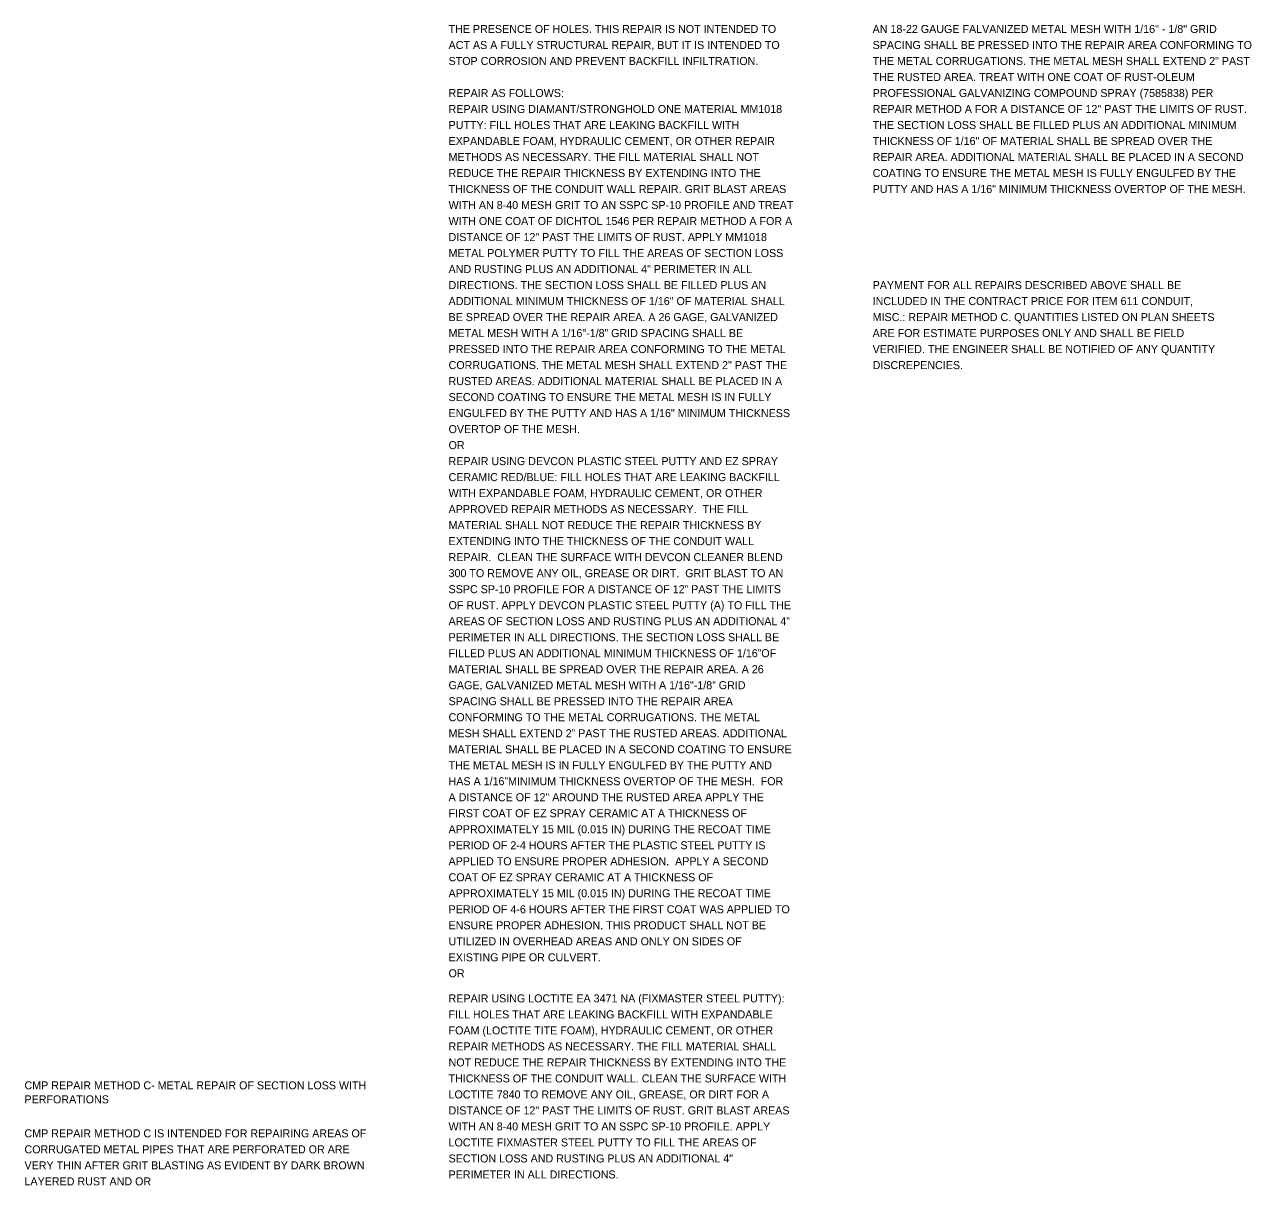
# Model space of a CAD drawing. Extents: x 0 to 34, y -22.7 to 22.
# Drawn here: x 9.82 to 31.29, y -22.66 to -2.35 of the extents above; entities that cross this region are included whole.
import ezdxf

# ---------------------------------------------------------------- set-up
doc = ezdxf.new("R2010")
doc.units = 0
doc.layers.add('SH_Text', color=7, linetype='Continuous')

msp = doc.modelspace()

# ---------------------------------------------------------------- texts
at = {"layer": 'SH_Text'}
for s, p in [('THE PRESENCE OF HOLES. THIS REPAIR IS NOT INTENDED TO ', (17.24, -2.502)), ('AN 18-22 GAUGE FALVANIZED METAL MESH WITH 1/16" - 1/8" GRID ', (24.66, -2.502)), ('ACT AS A FULLY STRUCTURAL REPAIR, BUT IT IS INTENDED TO ', (17.24, -2.782)), ('SPACING SHALL BE PRESSED INTO THE REPAIR AREA CONFORMING TO ', (24.66, -2.782)), ('STOP CORROSION AND PREVENT BACKFILL INFILTRATION.', (17.24, -3.062)), ('THE METAL CORRUGATIONS. THE METAL MESH SHALL EXTEND 2" PAST ', (24.66, -3.062)), ('THE RUSTED AREA. TREAT WITH ONE COAT OF RUST-OLEUM ', (24.66, -3.342)), ('REPAIR AS FOLLOWS:', (17.24, -3.622)), ('PROFESSIONAL GALVANIZING COMPOUND SPRAY (7585838) PER ', (24.66, -3.622)), ('REPAIR USING DIAMANT/STRONGHOLD ONE MATERIAL MM1018 ', (17.24, -3.902)), ('REPAIR METHOD A FOR A DISTANCE OF 12" PAST THE LIMITS OF RUST. ', (24.66, -3.902)), ('PUTTY: FILL HOLES THAT ARE LEAKING BACKFILL WITH ', (17.24, -4.182)), ('THE SECTION LOSS SHALL BE FILLED PLUS AN ADDITIONAL MINIMUM ', (24.66, -4.182)), ('EXPANDABLE FOAM, HYDRAULIC CEMENT, OR OTHER REPAIR ', (17.24, -4.462)), ('THICKNESS OF 1/16" OF MATERIAL SHALL BE SPREAD OVER THE ', (24.66, -4.462)), ('METHODS AS NECESSARY. THE FILL MATERIAL SHALL NOT ', (17.24, -4.742)), ('REPAIR AREA. ADDITIONAL MATERIAL SHALL BE PLACED IN A SECOND ', (24.66, -4.742)), ('REDUCE THE REPAIR THICKNESS BY EXTENDING INTO THE ', (17.24, -5.022)), ('COATING TO ENSURE THE METAL MESH IS FULLY ENGULFED BY THE ', (24.66, -5.022)), ('THICKNESS OF THE CONDUIT WALL REPAIR. GRIT BLAST AREAS ', (17.24, -5.302)), ('PUTTY AND HAS A 1/16" MINIMUM THICKNESS OVERTOP OF THE MESH.', (24.66, -5.302)), ('WITH AN 8-40 MESH GRIT TO AN SSPC SP-10 PROFILE AND TREAT ', (17.24, -5.582)), ('WITH ONE COAT OF DICHTOL 1546 PER REPAIR METHOD A FOR A ', (17.24, -5.862)), ('DISTANCE OF 12" PAST THE LIMITS OF RUST. APPLY MM1018 ', (17.24, -6.142)), ('METAL POLYMER PUTTY TO FILL THE AREAS OF SECTION LOSS ', (17.24, -6.422)), ('AND RUSTING PLUS AN ADDITIONAL 4" PERIMETER IN ALL ', (17.24, -6.702)), ('DIRECTIONS. THE SECTION LOSS SHALL BE FILLED PLUS AN ', (17.24, -6.982)), ('PAYMENT FOR ALL REPAIRS DESCRIBED ABOVE SHALL BE ', (24.66, -6.982)), ('ADDITIONAL MINIMUM THICKNESS OF 1/16" OF MATERIAL SHALL ', (17.24, -7.262)), ('INCLUDED IN THE CONTRACT PRICE FOR ITEM 611 CONDUIT, ', (24.66, -7.262)), ('BE SPREAD OVER THE REPAIR AREA. A 26 GAGE, GALVANIZED ', (17.24, -7.542)), ('MISC.: REPAIR METHOD C. QUANTITIES LISTED ON PLAN SHEETS ', (24.66, -7.542)), ('METAL MESH WITH A 1/16"-1/8” GRID SPACING SHALL BE ', (17.24, -7.822)), ('ARE FOR ESTIMATE PURPOSES ONLY AND SHALL BE FIELD ', (24.66, -7.822)), ('PRESSED INTO THE REPAIR AREA CONFORMING TO THE METAL ', (17.24, -8.102)), ('VERIFIED. THE ENGINEER SHALL BE NOTIFIED OF ANY QUANTITY ', (24.66, -8.102)), ('CORRUGATIONS. THE METAL MESH SHALL EXTEND 2" PAST THE ', (17.24, -8.382)), ('DISCREPENCIES.', (24.66, -8.382)), ('RUSTED AREAS. ADDITIONAL MATERIAL SHALL BE PLACED IN A ', (17.24, -8.662)), ('SECOND COATING TO ENSURE THE METAL MESH IS IN FULLY ', (17.24, -8.942)), ('ENGULFED BY THE PUTTY AND HAS A 1/16" MINIMUM THICKNESS ', (17.24, -9.222)), ('OVERTOP OF THE MESH. ', (17.24, -9.502)), ('OR', (17.24, -9.782)), ('REPAIR USING DEVCON PLASTIC STEEL PUTTY AND EZ SPRAY ', (17.24, -10.062)), ('CERAMIC RED/BLUE:\xa0FILL HOLES THAT ARE LEAKING BACKFILL ', (17.24, -10.342)), ('WITH EXPANDABLE FOAM, HYDRAULIC CEMENT, OR OTHER ', (17.24, -10.622)), ('APPROVED REPAIR METHODS AS NECESSARY. \xa0THE FILL ', (17.24, -10.902)), ('MATERIAL SHALL NOT REDUCE THE REPAIR THICKNESS BY ', (17.24, -11.182)), ('EXTENDING INTO THE THICKNESS OF THE CONDUIT WALL ', (17.24, -11.462)), ('REPAIR. \xa0CLEAN THE SURFACE WITH DEVCON CLEANER BLEND ', (17.24, -11.742)), ('300 TO REMOVE ANY OIL, GREASE OR DIRT. \xa0GRIT BLAST TO AN ', (17.24, -12.022)), ('SSPC SP-10 PROFILE\xa0FOR A DISTANCE OF 12” PAST THE LIMITS ', (17.24, -12.302)), ('OF RUST. APPLY DEVCON PLASTIC STEEL PUTTY (A) TO FILL THE ', (17.24, -12.582)), ('AREAS OF SECTION LOSS AND RUSTING PLUS AN ADDITIONAL 4” ', (17.24, -12.862)), ('PERIMETER IN ALL DIRECTIONS. THE SECTION LOSS SHALL BE ', (17.24, -13.142)), ('FILLED PLUS AN ADDITIONAL MINIMUM THICKNESS OF 1/16”OF ', (17.24, -13.422)), ('MATERIAL SHALL BE SPREAD OVER THE REPAIR AREA. A 26 ', (17.24, -13.702)), ('GAGE, GALVANIZED METAL MESH WITH A 1/16"-1/8” GRID ', (17.24, -13.982)), ('SPACING SHALL BE PRESSED INTO THE REPAIR AREA ', (17.24, -14.262)), ('CONFORMING TO THE METAL CORRUGATIONS. THE METAL ', (17.24, -14.542)), ('MESH SHALL EXTEND 2” PAST THE RUSTED AREAS. ADDITIONAL ', (17.24, -14.822)), ('MATERIAL SHALL BE PLACED IN A SECOND COATING TO ENSURE ', (17.24, -15.102)), ('THE METAL MESH IS IN FULLY ENGULFED BY THE PUTTY AND ', (17.24, -15.382)), ('HAS A 1/16”MINIMUM THICKNESS OVERTOP OF THE MESH. \xa0FOR ', (17.24, -15.662)), ('A DISTANCE OF 12" AROUND THE RUSTED AREA APPLY THE ', (17.24, -15.942)), ('FIRST COAT OF\xa0EZ SPRAY CERAMIC AT A THICKNESS OF ', (17.24, -16.222)), ('APPROXIMATELY 15 MIL (0.015 IN) DURING THE RECOAT TIME ', (17.24, -16.502)), ('PERIOD\xa0OF 2-4 HOURS\xa0AFTER\xa0THE PLASTIC STEEL PUTTY IS ', (17.24, -16.782)), ('APPLIED TO ENSURE PROPER ADHESION. \xa0APPLY A SECOND ', (17.24, -17.062)), ('COAT OF EZ SPRAY CERAMIC AT A THICKNESS OF ', (17.24, -17.342)), ('APPROXIMATELY 15 MIL (0.015 IN) DURING THE\xa0RECOAT\xa0TIME ', (17.24, -17.622)), ('PERIOD OF 4-6 HOURS AFTER THE FIRST COAT WAS APPLIED TO ', (17.24, -17.902)), ('ENSURE PROPER ADHESION. THIS PRODUCT SHALL NOT BE ', (17.24, -18.182)), ('UTILIZED IN OVERHEAD AREAS AND ONLY ON SIDES OF ', (17.24, -18.462)), ('EXISTING PIPE OR CULVERT.', (17.24, -18.742)), ('OR', (17.24, -19.022)), ('REPAIR USING LOCTITE EA 3471 NA (FIXMASTER STEEL PUTTY): ', (17.24, -19.461)), ('FILL HOLES THAT ARE LEAKING BACKFILL WITH EXPANDABLE ', (17.24, -19.741)), ('FOAM (LOCTITE TITE FOAM), HYDRAULIC CEMENT, OR OTHER ', (17.24, -20.021)), ('REPAIR METHODS AS NECESSARY. THE FILL MATERIAL SHALL ', (17.24, -20.301)), ('NOT REDUCE THE REPAIR THICKNESS BY EXTENDING INTO THE ', (17.24, -20.581)), ('THICKNESS OF THE CONDUIT WALL. CLEAN THE SURFACE WITH ', (17.24, -20.861)), ('CMP REPAIR METHOD C- METAL REPAIR OF SECTION LOSS WITH ', (9.82, -20.982)), ('LOCTITE 7840 TO REMOVE ANY OIL, GREASE, OR DIRT FOR A ', (17.24, -21.141)), ('PERFORATIONS', (9.82, -21.227)), ('DISTANCE OF 12" PAST THE LIMITS OF RUST. GRIT BLAST AREAS ', (17.24, -21.421)), ('CMP REPAIR METHOD C IS INTENDED FOR REPAIRING AREAS OF ', (9.82, -21.822)), ('WITH AN 8-40 MESH GRIT TO AN SSPC SP-10 PROFILE. APPLY ', (17.24, -21.701)), ('LOCTITE FIXMASTER STEEL PUTTY TO FILL THE AREAS OF ', (17.24, -21.981)), ('CORRUGATED METAL PIPES THAT ARE PERFORATED OR ARE  ', (9.82, -22.102)), ('VERY THIN AFTER GRIT BLASTING AS EVIDENT BY DARK BROWN ', (9.82, -22.382)), ('SECTION LOSS AND RUSTING PLUS AN ADDITIONAL 4" ', (17.24, -22.261)), ('LAYERED RUST AND OR ', (9.82, -22.662)), ('PERIMETER IN ALL DIRECTIONS. ', (17.24, -22.541))]:
    msp.add_text(s, height=0.14, dxfattribs=at).set_placement(p)

doc.saveas('drawing.dxf')
